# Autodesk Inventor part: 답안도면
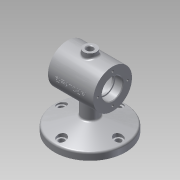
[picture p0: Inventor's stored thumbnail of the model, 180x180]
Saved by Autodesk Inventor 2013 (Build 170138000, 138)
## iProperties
Created: 2018-12
Part Number: 답안도면
Material: 알루미늄 6061
Document SubType Name: Modeling
Designer: Administrator
Density: 2.71 g/cm^3
Mass: 687.649 g
Surface Area: 555.483 cm^2
Volume: 253.745 cm^3
Author: Administrator
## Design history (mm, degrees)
sketch "스케치1"
  geometry: L1 (-35, 0)-(35, 0); L2 (35, 0)-(35, 30); L3 (35, 30)-(-35, 30); L4 (-35, 30)-(-35, 0); L5 (-35, 16)-(-23, 16); L6 (-23, 16)-(-23, 14); L7 (-23, 14)-(-20, 14); L8 (-20, 14)-(-20, 25); L9 (-20, 25)-(20, 25); L10 (20, 25)-(20, 14); L11 (20, 14)-(23, 14); L12 (23, 14)-(23, 16); L13 (23, 16)-(35, 16); 2 further points
  constraints: 26 end point, 6 parallel, 6 perpendicular, 4 collinear, 2 point on line, 1 coincident, 1 horizontal, 1 midpoint
  dimensions: "d0" = 70 distance of L2.end L3.end; "d2" = 60 diameter of L3 L1; "d3" = 28 diameter of L7 L1; "d4" = 50 diameter of L9 L1; "d5" = 32 diameter of L5 L1; "d6" = 12 distance of L5.start L5.end; "d7" = 40 distance of L8.end L9.end
revolve "회전1" sketch "스케치1" stored, may be unused: angle "d8" = 90 deg
sketch "스케치3"
  geometry: L1 (0, -26.988)-(0, -75); L2 (0, -75)-(55, -75); L3 (55, -75)-(55, -64); L4 (55, -64)-(12, -52.478); L5 (12, -52.478)-(12, -25.4); L6 (12, -25.4)-(0, -26.988); 1 further point
  constraints: 12 end point, 2 parallel, 1 perpendicular, 1 vertical, 1 vertical alignment
  dimensions: "d14" = 75 distance from line of L2 point (0, 0); "d15" = 11 distance of L2.end L3.end; "d16" = 75 deg angle of L3 L4; "d17" = 12 distance between parallel lines of L5 L1; "d18" = 55 distance of L1.end L2.end
revolve "회전2" sketch "스케치3" stored, may be unused: angle "d19" = 90 deg
node "작업 평면2"
sketch "스케치4"
  geometry: C1 r 10 at (0, 0); C2 r 5 at (0, 0); 1 further point
  constraints: 2 centre point, 2 coincident
  dimensions: "d21" = 20 diameter of C1; "d23" = 10 diameter of C2
extrude "돌출2" join sketch "스케치4" stored distance "d24" = 10; taper "d25" = 0 deg
feature "면 삭제1"
sketch "스케치5"
  geometry: C1 r 16 at (0, 0) reference; 1 further point
  constraints: 1 horizontal alignment
  dimensions: "d26" = 23 distance of C1.centre point (-23, 0)
hole "구멍1" sketch "스케치5" at (-23, 0) diameter "d27" = 3.242; stored, may be unused: countersink angle "d31" = 90 deg, drill point angle "d33" = 118 deg; dims "d28" = 8, "d29" = 4, "d30" = 2, "d32" = 10
fillet "모깎기1" dims "d37" = 3, "d53" = 0.3
chamfer "모따기1" distance "d38" = 1; stored, may be unused: second distance "d39" = 2, angle "d40" = 45 deg
node "작업 평면3"
sketch "스케치6"
  geometry: 3 further points
  constraints: 1 horizontal alignment
  dimensions: "d42" = 44 distance of point (-44, 0) point (0, 0)
hole "구멍2" sketch "스케치6" at (-44, 0), (-34.925, 88.9) diameter "d43" = 9; stored, may be unused: countersink angle "d47" = 90 deg, drill point angle "d49" = 118 deg; dims "d44" = 9, "d45" = 14, "d46" = 10, "d48" = 10
node "작업 평면4"
sketch "스케치7"
  geometry: L1 (-35, -30)-(-35, 30) reference; 2 further points
  constraints: 1 other
  dimensions: "d54" = 35 distance from line of point (0, 0) L1; "d55" = 30 vertical distance of L1.end point (0, 0)
feature "엠보싱1" sketch "스케치7" dims "d0" = 70, "d2" = 60, "d3" = 28, "d4" = 50, "d5" = 32, "d6" = 12, "d7" = 40, "d17" = 12, "d56" = 0.5, "d57" = 0
node "솔리드1"
pattern_circular "원형 패턴1" dims angle "d35" = 360 deg
mirror "대칭1"
pattern_circular "원형 패턴2" dims angle "d51" = 360 deg
other parameters: "d20" = 37
